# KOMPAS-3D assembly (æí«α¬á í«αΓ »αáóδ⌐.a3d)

Referenced files in D:\МОДЕЛЬ ТАНКА Т90\ДЕТАЛИ\КОРПУС\МЕТАЛЛ\КОРПУС ЛИТОЙ\: корпус борт правый.m3d, ступица балансира.m3d, гидроамартизатор.m3d, грязеочеститель.m3d, кронштейн опорного катка.m3d, посадка звездочки.m3d, посадка под линивец.m3d, упор балансира.m3d, прилив.m3d, посадка под вал звездочки.m3d
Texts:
  Сборка борт правый
  stalker61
